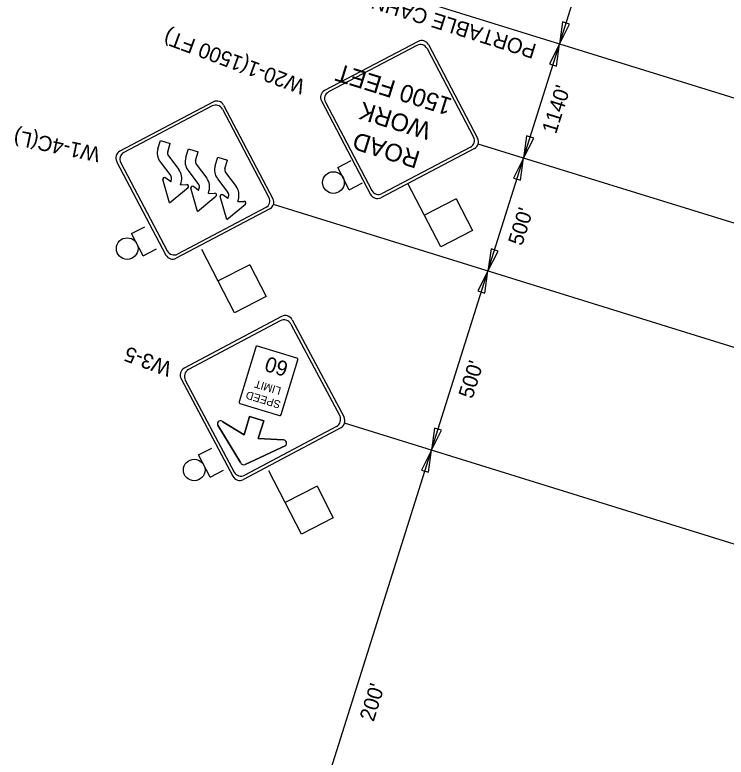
# Model space of a CAD drawing. Extents: x 2135767 to 2151731, y 141839 to 175894.
# Drawn here: x 2150920.9 to 2151203.3, y 148822.7 to 149117.3 of the extents above; entities that cross this region are included whole.
import ezdxf

# ---------------------------------------------------------------- set-up
doc = ezdxf.new("R2010")
doc.units = 0
for name, color, linetype in [('5', 7, 'Continuous'), ('Default', 7, 'Continuous'), ('PR_Dimensions', 7, 'Continuous'), ('PR_Dimensions_Phase', 7, 'Continuous'), ('PR_Phasing_Traffic_Control_Devices_1', 7, 'Continuous'), ('PR_Traffic_Control_Devices_Temp', 7, 'Continuous'), ('PR_Txt', 7, 'Continuous'), ('PR_Txt_Phase_1', 7, 'Continuous')]:
    doc.layers.add(name, color=color, linetype=linetype)

# ---------------------------------------------------------------- blocks, each defined once
blk = doc.blocks.new('Arrowhd')
at = {"layer": 'Default'}
blk.add_lwpolyline([(0.318, -0.053), (0.318, 0.053), (0, 0)], close=True, dxfattribs=at)
blk = doc.blocks.new('Cw20-1_none')
at = {"layer": 'Default'}
for p, q in [((0.177, 3.005), (2.651, 5.48)), ((5.48, 3.005), (3.005, 5.48)), ((0.318, 3.005), (2.651, 5.339)), ((5.338, 3.005), (3.005, 5.339)), ((2.651, 0.177), (0.177, 2.652)), ((2.651, 0.318), (0.318, 2.652)), ((3.005, 0.177), (5.48, 2.652)), ((3.005, 0.318), (5.338, 2.652))]:
    blk.add_line(p, q, dxfattribs=at)
for centre, start, end in [((2.828, 5.303), 45, 135), ((2.828, 5.162), 45, 135), ((0.353, 2.828), 135, 225), ((0.495, 2.828), 135, 225), ((5.162, 2.828), 315, 45), ((5.303, 2.828), 315, 45), ((2.828, 0.495), 225, 315), ((2.828, 0.354), 225, 315)]:
    blk.add_arc(centre, 0.25, start, end, dxfattribs=at)
for s, p in [('ROAD', (1.821, 3.637)), ('WORK', (1.751, 2.623))]:
    blk.add_text(s, height=0.5833, dxfattribs=at).set_placement(p)
blk = doc.blocks.new('FLSHFLAG')
at = {"layer": 'PR_Txt'}
for p, q in [((-1.202, 14.125), (0.838, 16.147)), ((0.838, 16.147), (4.9, 12.085)), ((0.819, 12.085), (-1.202, 14.125)), ((0.819, 12.085), (2.86, 14.106)), ((9.258, 14.004), (8.403, 13.149)), ((9.258, 14.004), (10.685, 12.576)), ((10.685, 12.576), (9.831, 11.722))]:
    blk.add_line(p, q, dxfattribs=at)
blk.add_circle((10.653, 13.836), 0.873, dxfattribs=at)
blk = doc.blocks.new('W3-5')
at = {"layer": '5'}
for p, q in [((0.808, 7.633), (6.735, 13.56)), ((13.56, 7.633), (7.633, 13.56)), ((6.735, 0.808), (0.808, 6.735)), ((7.633, 0.808), (13.56, 6.735))]:
    blk.add_line(p, q, dxfattribs=at)
for centre, start, end in [((7.184, 13.111), 45, 135), ((1.257, 7.184), 135, 225), ((13.111, 7.184), 315, 45), ((7.184, 1.257), 225, 315)]:
    blk.add_arc(centre, 0.635, start, end, dxfattribs=at)
at = {"layer": 'Default'}
for p, q in [((0.448, 7.633), (6.735, 13.919)), ((13.919, 7.633), (7.633, 13.919)), ((6.95, 12.723), (4.277, 10.304)), ((9.984, 10.322), (7.366, 12.687)), ((5.352, 8.019), (5.352, 3.415)), ((8.797, 8.13), (5.464, 8.13)), ((8.908, 3.415), (8.908, 8.019)), ((6.735, 0.449), (0.448, 6.735)), ((7.633, 0.449), (13.919, 6.735)), ((5.464, 3.304), (8.797, 3.304))]:
    blk.add_line(p, q, dxfattribs=at)
for points in [[(4.277, 10.304), (6.95, 12.723)], [(7.366, 12.687), (9.984, 10.322)], [(4.584, 9.924), (6.553, 10.412), (6.553, 8.913), (7.745, 8.913), (7.745, 10.448), (9.677, 9.96)], [(9.677, 9.96), (7.745, 10.448), (7.745, 8.913), (6.553, 8.913), (6.553, 10.412), (4.584, 9.924)]]:
    blk.add_lwpolyline(points, dxfattribs=at)
for centre, radius, start, end in [((7.184, 13.47), 0.635, 45, 135), ((7.141, 12.512), 0.285, 37.91416, 132.14933), ((7.141, 12.512), 0.285, 37.91416, 132.14933), ((4.519, 10.186), 0.269, 154.09026, 283.9085), ((4.519, 10.186), 0.269, 154.09026, 283.9085), ((9.825, 10.146), 0.237, 231.34169, 47.91235), ((9.825, 10.146), 0.237, 231.34169, 47.91235), ((5.464, 8.019), 0.111, 90, 180), ((8.797, 8.019), 0.111, 0, 90), ((0.897, 7.184), 0.635, 135, 225), ((13.47, 7.184), 0.635, 315, 45), ((5.464, 3.415), 0.111, 180, 270), ((8.797, 3.415), 0.111, 270, 0), ((7.184, 0.898), 0.635, 225, 315)]:
    blk.add_arc(centre, radius, start, end, dxfattribs=at)
for s, p in [('SPEED', (5.649, 6.987)), ('LIMIT', (5.945, 5.929))]:
    blk.add_text(s, height=0.635, dxfattribs=at).set_placement(p)

msp = doc.modelspace()

# ---------------------------------------------------------------- linework, layer by layer
at = {"layer": 'PR_Dimensions'}
for p, q in [((2151137.11, 149105.72), (2151152.1, 149153.3)), ((2151122.84, 149060.46), (2151137.11, 149105.72)), ((2151108.72, 149015.64), (2151122.84, 149060.46)), ((2150936.02, 148467.69), (2151108.72, 149015.64))]:
    msp.add_line(p, q, dxfattribs=at)
at = {"layer": 'PR_Dimensions_Phase'}
for p, q in [((2151310.48, 149051.85), (2151016.6, 149143.16)), ((2151296.5, 149006.77), (2151104.82, 149066.04)), ((2151282.52, 148961.69), (2151023.58, 149042.07)), ((2151260.42, 148890.44), (2151051.8, 148955.29))]:
    msp.add_line(p, q, dxfattribs=at)
at = {"layer": 'PR_Phasing_Traffic_Control_Devices_1'}
for p, q in [((2150999.74, 149082.77), (2150962.58, 149063.19)), ((2151003.79, 149081.51), (2151023.37, 149044.35)), ((2150999.23, 149081.15), (2150964.2, 149062.69)), ((2151003.29, 149079.89), (2151021.74, 149044.86)), ((2150977.71, 149064.18), (2150978.74, 149067.5)), ((2150978.74, 149067.5), (2150982.62, 149066.3)), ((2150981.59, 149062.98), (2150982.62, 149066.3)), ((2150988.75, 149060.76), (2150989.78, 149064.08)), ((2150988.75, 149060.76), (2150989.78, 149064.08)), ((2150988.75, 149060.76), (2150989.78, 149064.08)), ((2150989.78, 149064.08), (2150993.66, 149062.88)), ((2150989.78, 149064.08), (2150993.66, 149062.88)), ((2150989.78, 149064.08), (2150993.66, 149062.88)), ((2150981.87, 149061.41), (2150986.02, 149055.91)), ((2150992.63, 149059.56), (2150993.66, 149062.88)), ((2150992.63, 149059.56), (2150993.66, 149062.88)), ((2150992.63, 149059.56), (2150993.66, 149062.88)), ((2151000.4, 149057.5), (2151001.43, 149060.82)), ((2151001.43, 149060.82), (2151005.31, 149059.62)), ((2150961.32, 149059.14), (2150980.9, 149021.98)), ((2150962.94, 149058.63), (2150981.4, 149023.6)), ((2150978.63, 149058.97), (2150982.78, 149053.46)), ((2150992.9, 149057.99), (2150997.06, 149052.49)), ((2150992.9, 149057.99), (2150997.06, 149052.49)), ((2150992.9, 149057.99), (2150997.06, 149052.49)), ((2151004.28, 149056.3), (2151005.31, 149059.62)), ((2151005.31, 149059.62), (2151005.31, 149059.62)), ((2151005.31, 149059.62), (2151005.31, 149059.62)), ((2151005.31, 149059.62), (2151005.31, 149059.62)), ((2151005.31, 149059.62), (2151005.31, 149059.62)), ((2150989.66, 149055.55), (2150993.82, 149050.04)), ((2150989.66, 149055.55), (2150993.82, 149050.04)), ((2150989.66, 149055.55), (2150993.82, 149050.04)), ((2151004.55, 149054.74), (2151008.71, 149049.23)), ((2150982.33, 149042.71), (2150979.68, 149051.9)), ((2150982.8, 149051.06), (2150980.81, 149052.55)), ((2150982.8, 149051.06), (2150983.05, 149051.9)), ((2151001.31, 149052.29), (2151005.47, 149046.79)), ((2150982.33, 149042.71), (2150989.72, 149048.79)), ((2150986.67, 149049.86), (2150986.93, 149050.7)), ((2150986.67, 149049.86), (2150989.15, 149049.96)), ((2150993.84, 149047.64), (2150991.85, 149049.13)), ((2150993.84, 149047.64), (2150991.85, 149049.13)), ((2150993.84, 149047.64), (2150991.85, 149049.13)), ((2150993.37, 149039.29), (2150990.72, 149048.48)), ((2150993.37, 149039.29), (2150990.72, 149048.48)), ((2150993.37, 149039.29), (2150990.72, 149048.48)), ((2150993.84, 149047.64), (2150994.09, 149048.48)), ((2150993.84, 149047.64), (2150994.09, 149048.48)), ((2150993.84, 149047.64), (2150994.09, 149048.48)), ((2150997.71, 149046.44), (2150997.97, 149047.28)), ((2150997.71, 149046.44), (2150997.97, 149047.28)), ((2150997.71, 149046.44), (2150997.97, 149047.28)), ((2150997.71, 149046.44), (2151000.19, 149046.54)), ((2150997.71, 149046.44), (2151000.19, 149046.54)), ((2150997.71, 149046.44), (2151000.19, 149046.54)), ((2151005.48, 149044.39), (2151003.49, 149045.87)), ((2150993.37, 149039.29), (2151000.75, 149045.37)), ((2150993.37, 149039.29), (2151000.75, 149045.37)), ((2150993.37, 149039.29), (2151000.75, 149045.37)), ((2151005.02, 149036.03), (2151002.37, 149045.23)), ((2151005.48, 149044.39), (2151005.74, 149045.22)), ((2151009.36, 149043.19), (2151009.62, 149044.02)), ((2151009.36, 149043.19), (2151011.84, 149043.29)), ((2151022.11, 149040.3), (2150984.95, 149020.72)), ((2151020.49, 149040.8), (2150985.45, 149022.34)), ((2151005.02, 149036.03), (2151012.4, 149042.12))]:
    msp.add_line(p, q, dxfattribs=at)
for centre, radius, start, end in [((2151000.63, 149078.49), 3, 27.7835, 117.7835), ((2151001.13, 149080.11), 3, 27.7835, 117.7835), ((2150983.25, 149062.46), 5.8, 162.7835, 217.0513), ((2150963.98, 149060.53), 3, 117.7835, 207.7835), ((2150965.6, 149060.03), 3, 117.7835, 207.7835), ((2150983.25, 149062.46), 1.74, 162.7835, 217.0513), ((2150994.29, 149059.04), 5.8, 162.7835, 217.0513), ((2150994.29, 149059.04), 5.8, 162.7835, 217.0513), ((2150994.29, 149059.04), 5.8, 162.7835, 217.0513), ((2150994.29, 149059.04), 1.74, 162.7835, 217.0513), ((2150994.29, 149059.04), 1.74, 162.7835, 217.0513), ((2150994.29, 149059.04), 1.74, 162.7835, 217.0513), ((2150981.39, 149052.41), 5.8, 342.7835, 37.0513), ((2151005.94, 149055.79), 5.8, 162.7835, 217.0513), ((2151005.94, 149055.79), 1.74, 162.7835, 217.0513), ((2150980.36, 149052.02), 0.689, 49.6345, 201.9001), ((2150981.39, 149052.41), 1.74, 342.7835, 37.0513), ((2150992.43, 149048.99), 5.8, 342.7835, 37.0513), ((2150992.43, 149048.99), 5.8, 342.7835, 37.0513), ((2150992.43, 149048.99), 5.8, 342.7835, 37.0513), ((2150989.23, 149049.28), 0.689, 303.6669, 95.9326), ((2150991.4, 149048.6), 0.689, 49.6345, 201.9001), ((2150991.4, 149048.6), 0.689, 49.6345, 201.9001), ((2150991.4, 149048.6), 0.689, 49.6345, 201.9001), ((2150992.43, 149048.99), 1.74, 342.7835, 37.0513), ((2150992.43, 149048.99), 1.74, 342.7835, 37.0513), ((2150992.43, 149048.99), 1.74, 342.7835, 37.0513), ((2151004.08, 149045.74), 5.8, 342.7835, 37.0513), ((2151000.26, 149045.86), 0.689, 303.6669, 95.9326), ((2151000.26, 149045.86), 0.689, 303.6669, 95.9326), ((2151000.26, 149045.86), 0.689, 303.6669, 95.9326), ((2151003.05, 149045.35), 0.689, 49.6345, 201.9001), ((2151004.08, 149045.74), 1.74, 342.7835, 37.0513), ((2151011.91, 149042.6), 0.689, 303.6669, 95.9326), ((2151019.09, 149043.46), 3, 297.7835, 27.7835), ((2151020.71, 149042.95), 3, 297.7835, 27.7835), ((2150984.06, 149025), 3, 207.7835, 297.7835), ((2150983.55, 149023.38), 3, 207.7835, 297.7835)]:
    msp.add_arc(centre, radius, start, end, dxfattribs=at)

# ---------------------------------------------------------------- block references
at = {"layer": 'PR_Dimensions', "xscale": 27.559000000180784, "yscale": 27.559000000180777}
for p, rotation in [((2151137.11, 149105.72), 72.57227732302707), ((2151137.11, 149105.72), -107.4277226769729), ((2151122.84, 149060.46), 72.57227732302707), ((2151122.84, 149060.46), -107.4277226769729), ((2151108.72, 149015.64), 72.57227732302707), ((2151108.72, 149015.64), -107.4277226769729), ((2151086.31, 148944.52), 72.57227732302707), ((2151086.32, 148944.56), -107.4277226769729)]:
    msp.add_blockref('Arrowhd', p, dxfattribs=dict(at, rotation=rotation))
at = {"layer": 'PR_Phasing_Traffic_Control_Devices_1', "xscale": 4.921250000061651, "yscale": 4.921250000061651, "rotation": 162.41849638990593}
msp.add_blockref('FLSHFLAG', (2151036.05, 149073.61), dxfattribs=at)
at = {"layer": 'PR_Traffic_Control_Devices_Temp'}
for name, p, xscale, yscale, rotation in [('Cw20-1_none', (2151116.09, 149098.08), 11.999999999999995, 11.999999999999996, 162.72081903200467), ('FLSHFLAG', (2151117.96, 149099.76), 4.921250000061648, 4.921250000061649, 162.35580171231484), ('W3-5', (2151063.36, 148988.73), 4.921250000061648, 4.921250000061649, 163.0193420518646), ('FLSHFLAG', (2151062.66, 148985.76), 4.921250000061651, 4.921250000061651, 162.41849638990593)]:
    msp.add_blockref(name, p, dxfattribs=dict(at, xscale=xscale, yscale=yscale, rotation=rotation))

# ---------------------------------------------------------------- texts
for s, height, rotation, p in [('1500 FEET', 7, 162.7208, (2151094.92, 149083.94)), ('60', 6, 163.3844, (2151029.88, 148979.34))]:
    msp.add_text(s, height=height, rotation=rotation, dxfattribs=at).set_placement(p)
at = {"layer": 'PR_Txt'}
for s, rotation, p in [('PORTABLE CAHNGEABLE', 162.5723, (2151128.37, 149105.48)), ("1140'", 72.5723, (2151135.71, 149069.7)), ("500'", 72.5723, (2151122.26, 149025.35)), ("500'", 72.5723, (2151102.55, 148964.64)), ("200'", 72.5723, (2151063.32, 148836.55))]:
    msp.add_text(s, height=6, rotation=rotation, dxfattribs=at).set_placement(p)
at = {"layer": 'PR_Txt_Phase_1'}
for s, rotation, p in [('W20-1(1500 FT)', 159.7012, (2151036.62, 149091.24)), ('W1-4C(L)', 168.1419, (2150955.16, 149064.62)), ('W3-5', 159.7012, (2150983.73, 148979.22))]:
    msp.add_text(s, height=6, rotation=rotation, dxfattribs=at).set_placement(p)

doc.saveas('drawing.dxf')
